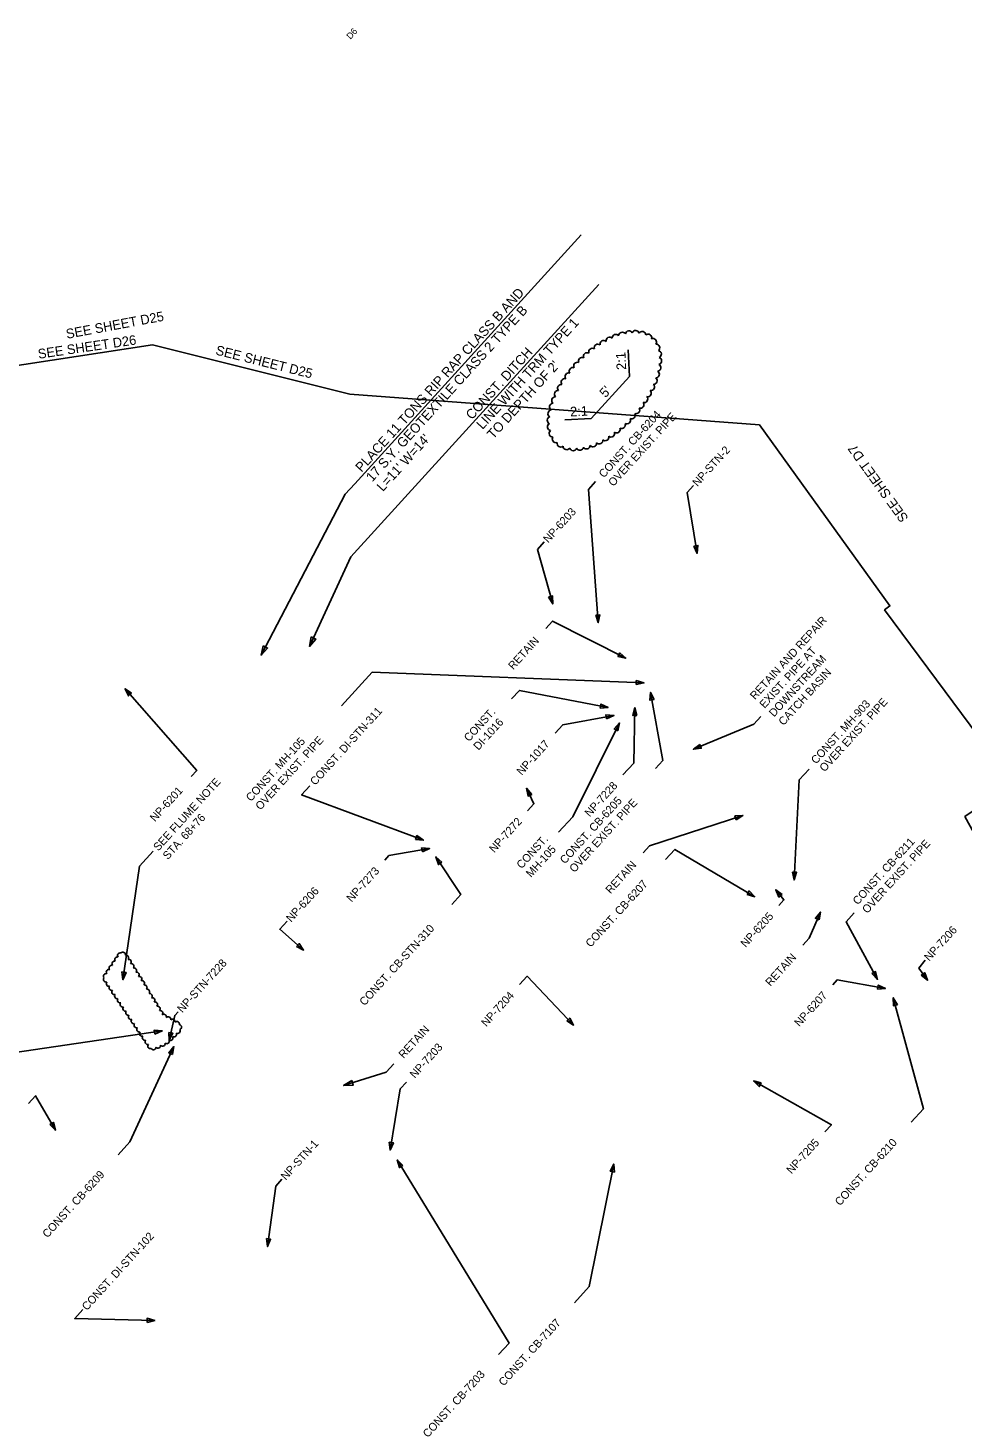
# Model space of a CAD drawing. Extents: x 1608866 to 1610566, y 1091738 to 1093850.
# Drawn here: x 1609658 to 1610242, y 1092975 to 1093850 of the extents above; entities that cross this region are included whole.
import ezdxf

# ---------------------------------------------------------------- set-up
doc = ezdxf.new("R2010")
doc.units = 0
for name, color, linetype in [('Default', 7, 'Continuous'), ('Level 27', 7, 'Continuous'), ('Plan_Clip', 7, 'Continuous'), ('RD_SHT_Bndy', 7, 'Continuous'), ('RD_SHT_MatchLine', 7, 'Continuous'), ('RD_TX_Drainage', 7, 'Continuous')]:
    doc.layers.add(name, color=color, linetype=linetype)

msp = doc.modelspace()

# ---------------------------------------------------------------- linework, layer by layer
at = {"layer": 'Default'}
msp.add_lwpolyline([(1610029.9, 1093383.53), (1610036.58, 1093390.87), (1610037.37, 1093425.47)], dxfattribs=at)
msp.add_lwpolyline([(1610038.55, 1093420.61), (1610037.37, 1093425.47), (1610035.97, 1093420.67)], close=True, dxfattribs=at)
at = {"layer": 'Level 27'}
for p, q in [((1610034.03, 1093632.49), (1610033.24, 1093649.09)), ((1610034.03, 1093632.49), (1610010.12, 1093606.2)), ((1610010.12, 1093606.2), (1609993.52, 1093605.42))]:
    msp.add_line(p, q, dxfattribs=at)
for centre, start, end in [((1610033.61, 1093658.68), 25.47578, 170.47578), ((1610037.8, 1093658.89), 15.48659, 160.48659), ((1610014.21, 1093650.33), 52.27043, 197.27043), ((1610017.81, 1093652.65), 48.45134, 193.45134), ((1610021.55, 1093654.71), 44.14815, 189.14815), ((1610025.44, 1093656.45), 39.14001, 184.14001), ((1610029.47, 1093657.81), 33.09132, 178.09132), ((1610041.89, 1093658.27), 2.08013, 147.08013), ((1610045.61, 1093656.61), 344.80506, 129.80506), ((1610048.59, 1093653.89), 325.62249, 110.62249), ((1610050.6, 1093650.35), 308.34742, 93.34742), ((1610004.35, 1093642.1), 62.15062, 207.15062), ((1610007.48, 1093645.03), 59.02235, 204.02235), ((1610010.77, 1093647.78), 55.75745, 200.75745), ((1610051.61, 1093646.33), 294.94096, 79.94096), ((1610051.79, 1093642.15), 284.95177, 69.95177), ((1609998.58, 1093635.76), 68.27724, 213.27724), ((1610001.38, 1093639.01), 65.21387, 210.21387), ((1610050.35, 1093633.8), 271.28754, 56.28754), ((1610051.32, 1093637.94), 277.33623, 62.33623), ((1609991.32, 1093625.16), 78.15719, 223.15719), ((1609993.53, 1093628.83), 74.6705, 219.6705), ((1609995.96, 1093632.36), 71.40568, 216.40568), ((1610047.29, 1093625.84), 261.97621, 46.97621), ((1610048.98, 1093629.76), 266.27939, 51.27939), ((1609987.65, 1093617.44), 86.27835, 231.27835), ((1609989.35, 1093621.36), 81.97595, 226.97595), ((1610043.1, 1093618.37), 254.6701, 39.6701), ((1610045.31, 1093622.04), 258.15711, 43.15711), ((1609985.31, 1093609.26), 97.33161, 242.33161), ((1609986.28, 1093613.4), 91.28497, 236.28497), ((1610035.25, 1093608.19), 245.21367, 30.21367), ((1610038.06, 1093611.44), 248.27692, 33.27692), ((1610040.68, 1093614.84), 251.4052, 36.4052), ((1609984.85, 1093605.06), 104.94501, 249.94501), ((1609985.02, 1093600.87), 114.93498, 259.93498), ((1610025.86, 1093599.42), 235.75705, 20.75705), ((1610029.15, 1093602.17), 239.02187, 24.02187), ((1610032.28, 1093605.1), 242.15031, 27.15031), ((1609986.03, 1093596.86), 128.3407, 273.3407), ((1609988.04, 1093593.31), 145.61713, 290.61713), ((1609991.03, 1093590.59), 164.81042, 309.81042), ((1610015.08, 1093592.49), 224.14919, 9.14919), ((1610018.83, 1093594.55), 228.4516, 13.4516), ((1610022.42, 1093596.87), 232.27036, 17.27036), ((1609994.75, 1093588.93), 182.08684, 327.08684), ((1609998.84, 1093588.31), 195.49257, 340.49257), ((1610003.02, 1093588.53), 205.48254, 350.48254), ((1610007.16, 1093589.39), 213.09594, 358.09594), ((1610011.19, 1093590.75), 219.14258, 4.14258)]:
    msp.add_arc(centre, 2.27, start, end, dxfattribs=at)
at = {"layer": 'Plan_Clip'}
msp.add_lwpolyline([(1608865.54, 1092773.4), (1609640.55, 1093637.57), (1609735.98, 1093652.25), (1609859.36, 1093621.37), (1610115.12, 1093602.27), (1610196.6, 1093489.1), (1610193.26, 1093486.62), (1610273.82, 1093378.23), (1610243.45, 1093357.42), (1610329.63, 1093200.98), (1610402.66, 1093068.39), (1609510.9, 1092089.32), (1609496.88, 1092101.66), (1609489.45, 1092107.95), (1609480.57, 1092093.35), (1609450.27, 1092115.95), (1609446.7, 1092110.96), (1609379.78, 1092159.35), (1609135.57, 1092347.04), (1609149.57, 1092364.39), (1609089.98, 1092453.43), (1608942.04, 1092657.59), (1608947.36, 1092661.14)], close=True, dxfattribs=at)
msp.add_lwpolyline([(1608865.54, 1092773.4), (1609640.55, 1093637.57), (1609735.98, 1093652.25), (1609859.36, 1093621.37), (1610115.12, 1093602.27), (1610196.6, 1093489.1), (1610193.26, 1093486.62), (1610273.82, 1093378.23), (1610243.45, 1093357.42), (1610329.63, 1093200.98), (1610402.66, 1093068.39), (1609510.9, 1092089.32), (1609496.88, 1092101.66), (1609489.45, 1092107.95), (1609480.57, 1092093.35), (1609450.27, 1092115.95), (1609446.7, 1092110.96), (1609379.78, 1092159.35), (1609135.57, 1092347.04), (1609149.57, 1092364.39), (1609089.98, 1092453.43), (1608942.04, 1092657.59), (1608947.36, 1092661.14)], close=True, dxfattribs=at)
msp.add_lwpolyline([(1608865.54, 1092773.4), (1609640.55, 1093637.57), (1609735.98, 1093652.25), (1609859.36, 1093621.37), (1610115.12, 1093602.27), (1610196.6, 1093489.1), (1610193.26, 1093486.62), (1610273.82, 1093378.23), (1610243.45, 1093357.42), (1610329.63, 1093200.98), (1610402.66, 1093068.39), (1609510.9, 1092089.32), (1609496.88, 1092101.66), (1609489.45, 1092107.95), (1609480.57, 1092093.35), (1609450.27, 1092115.95), (1609446.7, 1092110.96), (1609379.78, 1092159.35), (1609135.57, 1092347.04), (1609149.57, 1092364.39), (1609089.98, 1092453.43), (1608942.04, 1092657.59), (1608947.36, 1092661.14)], close=True, dxfattribs=at)
msp.add_lwpolyline([(1608865.54, 1092773.4), (1609640.55, 1093637.57), (1609735.98, 1093652.25), (1609859.36, 1093621.37), (1610115.12, 1093602.27), (1610196.6, 1093489.1), (1610193.26, 1093486.62), (1610273.82, 1093378.23), (1610243.45, 1093357.42), (1610329.63, 1093200.98), (1610402.66, 1093068.39), (1609510.9, 1092089.32), (1609496.88, 1092101.66), (1609489.45, 1092107.95), (1609480.57, 1092093.35), (1609450.27, 1092115.95), (1609446.7, 1092110.96), (1609379.78, 1092159.35), (1609135.57, 1092347.04), (1609149.57, 1092364.39), (1609089.98, 1092453.43), (1608942.04, 1092657.59), (1608947.36, 1092661.14)], close=True, dxfattribs=at)
msp.add_lwpolyline([(1608865.54, 1092773.4), (1609640.55, 1093637.57), (1609735.98, 1093652.25), (1609859.36, 1093621.37), (1610115.12, 1093602.27), (1610196.6, 1093489.1), (1610193.26, 1093486.62), (1610273.82, 1093378.23), (1610243.45, 1093357.42), (1610329.63, 1093200.98), (1610402.66, 1093068.39), (1609510.9, 1092089.32), (1609496.88, 1092101.66), (1609489.45, 1092107.95), (1609480.57, 1092093.35), (1609450.27, 1092115.95), (1609446.7, 1092110.96), (1609379.78, 1092159.35), (1609135.57, 1092347.04), (1609149.57, 1092364.39), (1609089.98, 1092453.43), (1608942.04, 1092657.59), (1608947.36, 1092661.14)], close=True, dxfattribs=at)
msp.add_lwpolyline([(1608865.54, 1092773.4), (1609640.55, 1093637.57), (1609735.98, 1093652.25), (1609859.36, 1093621.37), (1610115.12, 1093602.27), (1610196.6, 1093489.1), (1610193.26, 1093486.62), (1610273.82, 1093378.23), (1610243.45, 1093357.42), (1610329.63, 1093200.98), (1610402.66, 1093068.39), (1609510.9, 1092089.32), (1609496.88, 1092101.66), (1609489.45, 1092107.95), (1609480.57, 1092093.35), (1609450.27, 1092115.95), (1609446.7, 1092110.96), (1609379.78, 1092159.35), (1609135.57, 1092347.04), (1609149.57, 1092364.39), (1609089.98, 1092453.43), (1608942.04, 1092657.59), (1608947.36, 1092661.14)], close=True, dxfattribs=at)
msp.add_lwpolyline([(1608865.54, 1092773.4), (1609640.55, 1093637.57), (1609735.98, 1093652.25), (1609859.36, 1093621.37), (1610115.12, 1093602.27), (1610196.6, 1093489.1), (1610193.26, 1093486.62), (1610273.82, 1093378.23), (1610243.45, 1093357.42), (1610329.63, 1093200.98), (1610402.66, 1093068.39), (1609510.9, 1092089.32), (1609496.88, 1092101.66), (1609489.45, 1092107.95), (1609480.57, 1092093.35), (1609450.27, 1092115.95), (1609446.7, 1092110.96), (1609379.78, 1092159.35), (1609135.57, 1092347.04), (1609149.57, 1092364.39), (1609089.98, 1092453.43), (1608942.04, 1092657.59), (1608947.36, 1092661.14)], close=True, dxfattribs=at)
msp.add_lwpolyline([(1608865.54, 1092773.4), (1609640.55, 1093637.57), (1609735.98, 1093652.25), (1609859.36, 1093621.37), (1610115.12, 1093602.27), (1610196.6, 1093489.1), (1610193.26, 1093486.62), (1610273.82, 1093378.23), (1610243.45, 1093357.42), (1610329.63, 1093200.98), (1610402.66, 1093068.39), (1609510.9, 1092089.32), (1609496.88, 1092101.66), (1609489.45, 1092107.95), (1609480.57, 1092093.35), (1609450.27, 1092115.95), (1609446.7, 1092110.96), (1609379.78, 1092159.35), (1609135.57, 1092347.04), (1609149.57, 1092364.39), (1609089.98, 1092453.43), (1608942.04, 1092657.59), (1608947.36, 1092661.14)], close=True, dxfattribs=at)
at = {"layer": 'RD_TX_Drainage'}
for p, q in [((1610003.81, 1093720.88), (1609862.33, 1093565.32)), ((1610014.76, 1093689.89), (1609935.98, 1093603.27))]:
    msp.add_line(p, q, dxfattribs=at)
for points in [[(1609935.98, 1093603.27), (1609859.96, 1093519.69), (1609834.12, 1093463.76)], [(1609862.33, 1093565.32), (1609856.42, 1093558.82), (1609803.85, 1093458.34)], [(1610012.74, 1093566.71), (1610008.29, 1093561.81), (1610014.5, 1093478.62)], [(1610073.91, 1093564.26), (1610069.92, 1093559.88), (1610076.19, 1093521.87)], [(1609980.7, 1093529.02), (1609976.45, 1093524.35), (1609986.01, 1093490.29)], [(1609981.71, 1093474.91), (1609985.93, 1093479.56), (1610031.66, 1093456.35)], [(1609854.19, 1093426.57), (1609873.31, 1093447.59), (1610042.94, 1093440.99)], [(1609760.28, 1093382.5), (1609763.64, 1093386.19), (1609718.87, 1093437.35)], [(1609960.34, 1093430.93), (1609965.23, 1093436.31), (1610020.56, 1093425.59)], [(1610050.3, 1093387.54), (1610054.89, 1093392.59), (1610047.15, 1093435.08)], [(1609987.45, 1093409.54), (1609992.28, 1093414.85), (1610024.19, 1093420.71)], [(1610116.07, 1093420.03), (1610111.64, 1093415.15), (1610073.85, 1093399.54)], [(1609989.7, 1093347.67), (1609998.5, 1093357.35), (1610027.72, 1093415.96)], [(1610146.1, 1093387.13), (1610139.95, 1093380.37), (1610136.78, 1093317.92)], [(1609834.28, 1093376.6), (1609829.18, 1093370.98), (1609905.23, 1093342.72)], [(1609970.26, 1093361.13), (1609974.24, 1093365.52), (1609969.69, 1093375.16)], [(1610042.48, 1093334.91), (1610046.4, 1093339.21), (1610104.79, 1093358.16)], [(1609881.19, 1093330.27), (1609883.75, 1093333.08), (1609909.12, 1093337.49)], [(1609736.51, 1093335.8), (1609727.95, 1093326.39), (1609717.56, 1093255.5)], [(1609922.92, 1093302.5), (1609928.57, 1093308.71), (1609913.01, 1093332.25)], [(1610056.56, 1093330.65), (1610062.32, 1093336.98), (1610112.19, 1093307.42)], [(1610127.34, 1093301.96), (1610130.44, 1093305.38), (1610125.3, 1093311.72)], [(1610142.33, 1093277.13), (1610146.25, 1093281.43), (1610153.21, 1093297.83)], [(1610174.28, 1093297.23), (1610169.26, 1093291.72), (1610188.87, 1093255.71)], [(1609820.13, 1093292.08), (1609815.54, 1093287.04), (1609830.46, 1093274.01)], [(1610218.69, 1093267.71), (1610214.69, 1093262.69), (1610220.13, 1093255.23)], [(1609965.29, 1093252.45), (1609970.06, 1093257.7), (1609999.04, 1093227.2)], [(1610160.91, 1093252.43), (1610163.61, 1093255.4), (1610193.82, 1093250.09)], [(1610209.87, 1093166.5), (1610217.52, 1093174.91), (1610198.75, 1093244.25)], [(1609752.08, 1093235.51), (1609749.96, 1093233.19), (1609746.51, 1093217.64)], [(1609644.62, 1093205.17), (1609648.79, 1093209.76), (1609742.13, 1093223.53)], [(1609714.62, 1093146.19), (1609721.98, 1093154.28), (1609749.4, 1093213.76)], [(1609886.71, 1093202.91), (1609882.08, 1093197.82), (1609855.42, 1093189.41)], [(1609894.69, 1093191.57), (1609890.8, 1093187.29), (1609884.44, 1093149.08)], [(1610155.96, 1093160.45), (1610160.07, 1093164.97), (1610111.46, 1093192.29)], [(1609658.61, 1093178.3), (1609662.94, 1093183.07), (1609675.47, 1093161.51)], [(1609952.21, 1093021.36), (1609958.75, 1093028.55), (1609888.87, 1093142.97)], [(1609999.57, 1093053.57), (1610008.85, 1093063.77), (1610024.18, 1093140.34)], [(1609816.83, 1093130.86), (1609813, 1093126.65), (1609807.9, 1093088.82)], [(1609692.58, 1093049.44), (1609687.5, 1093043.86), (1609737.47, 1093042.58)]]:
    msp.add_lwpolyline(points, dxfattribs=at)
for points in [[(1610074.13, 1093526.42), (1610076.19, 1093521.87), (1610076.68, 1093526.85)], [(1609983.46, 1093494.59), (1609986.01, 1093490.29), (1609985.95, 1093495.29)], [(1610012.85, 1093483.34), (1610014.5, 1093478.62), (1610015.43, 1093483.54)], [(1609835.14, 1093469.67), (1609834.12, 1093463.76), (1609837.96, 1093468.37)], [(1609805.16, 1093464.19), (1609803.85, 1093458.34), (1609807.91, 1093462.75)], [(1610026.76, 1093457.39), (1610031.66, 1093456.35), (1610027.94, 1093459.69)], [(1610038.06, 1093439.88), (1610042.94, 1093440.99), (1610038.16, 1093442.47)], [(1609723.02, 1093434.57), (1609718.87, 1093437.35), (1609721.08, 1093432.86)], [(1610049.29, 1093430.56), (1610047.15, 1093435.08), (1610046.75, 1093430.1)], [(1610015.58, 1093425.24), (1610020.56, 1093425.59), (1610016.07, 1093427.78)], [(1610019.68, 1093418.57), (1610024.19, 1093420.71), (1610019.21, 1093421.11)], [(1610026.72, 1093411.06), (1610027.72, 1093415.96), (1610024.41, 1093412.22)], [(1610077.82, 1093402.58), (1610073.85, 1093399.54), (1610078.81, 1093400.19)], [(1609972.92, 1093371.35), (1609969.69, 1093375.16), (1609970.58, 1093370.24)], [(1610100.6, 1093355.43), (1610104.79, 1093358.16), (1610099.8, 1093357.9)], [(1609900.26, 1093343.19), (1609905.23, 1093342.72), (1609901.16, 1093345.61)], [(1609904.58, 1093335.38), (1609909.12, 1093337.49), (1609904.14, 1093337.93)], [(1609916.75, 1093328.94), (1609913.01, 1093332.25), (1609914.59, 1093327.51)], [(1610135.74, 1093322.81), (1610136.78, 1093317.92), (1610138.32, 1093322.68)], [(1610129.35, 1093308.78), (1610125.3, 1093311.72), (1610127.34, 1093307.15)], [(1610107.37, 1093308.77), (1610112.19, 1093307.42), (1610108.69, 1093311)], [(1610152.51, 1093292.88), (1610153.21, 1093297.83), (1610150.13, 1093293.89)], [(1609825.97, 1093276.21), (1609830.46, 1093274.01), (1609827.67, 1093278.16)], [(1609716.98, 1093260.46), (1609717.56, 1093255.5), (1609719.54, 1093260.09)], [(1610185.42, 1093259.33), (1610188.87, 1093255.71), (1610187.7, 1093260.57)], [(1610216.24, 1093258.37), (1610220.13, 1093255.23), (1610218.33, 1093259.9)], [(1610188.84, 1093249.65), (1610193.82, 1093250.09), (1610189.29, 1093252.2)], [(1610201.26, 1093239.93), (1610198.75, 1093244.25), (1610198.77, 1093239.25)], [(1609737.54, 1093221.55), (1609742.13, 1093223.53), (1609737.16, 1093224.11)], [(1609994.77, 1093229.81), (1609999.04, 1093227.2), (1609996.65, 1093231.6)], [(1609746.29, 1093222.64), (1609746.51, 1093217.64), (1609748.82, 1093222.08)], [(1609748.55, 1093208.83), (1609749.4, 1093213.76), (1609746.2, 1093209.92)], [(1609860.48, 1093192.63), (1609855.42, 1093189.41), (1609861.42, 1093189.67)], [(1610116.31, 1093191.05), (1610111.46, 1093192.29), (1610115.04, 1093188.8)], [(1609671.93, 1093165.03), (1609675.47, 1093161.51), (1609674.17, 1093166.33)], [(1609883.96, 1093154.06), (1609884.44, 1093149.08), (1609886.51, 1093153.64)], [(1609892.49, 1093139.52), (1609888.87, 1093142.97), (1609890.28, 1093138.18)], [(1610024.5, 1093135.35), (1610024.18, 1093140.34), (1610021.96, 1093135.85)], [(1609807.26, 1093093.78), (1609807.9, 1093088.82), (1609809.83, 1093093.43)], [(1609732.61, 1093041.41), (1609737.47, 1093042.58), (1609732.67, 1093043.99)]]:
    msp.add_lwpolyline(points, close=True, dxfattribs=at)
for centre, start, end in [((1609714.1, 1093268.09), 73.34641, 218.34641), ((1609715.85, 1093270.67), 73.34641, 218.34641), ((1609717.51, 1093271.11), 351.27368, 136.27368), ((1609719.52, 1093269.27), 319.10662, 104.10662), ((1609721.16, 1093266.61), 319.10662, 104.10662), ((1609707.08, 1093257.74), 73.34641, 218.34641), ((1609708.84, 1093260.33), 73.34641, 218.34641), ((1609710.59, 1093262.91), 73.34641, 218.34641), ((1609712.35, 1093265.5), 73.34641, 218.34641), ((1609722.8, 1093263.95), 319.10662, 104.10662), ((1609724.44, 1093261.29), 319.10662, 104.10662), ((1609726.07, 1093258.63), 319.10662, 104.10662), ((1609707.07, 1093255.7), 141.18178, 286.18178), ((1609708.81, 1093253.1), 141.18178, 286.18178), ((1609710.54, 1093250.5), 141.18178, 286.18178), ((1609727.71, 1093255.97), 319.10662, 104.10662), ((1609729.35, 1093253.31), 319.10662, 104.10662), ((1609730.99, 1093250.64), 319.10662, 104.10662), ((1609712.27, 1093247.9), 141.18178, 286.18178), ((1609714.01, 1093245.3), 141.18178, 286.18178), ((1609715.74, 1093242.7), 141.18178, 286.18178), ((1609717.47, 1093240.1), 141.18178, 286.18178), ((1609732.62, 1093247.98), 319.10662, 104.10662), ((1609734.26, 1093245.32), 319.10662, 104.10662), ((1609735.9, 1093242.66), 319.10662, 104.10662), ((1609737.54, 1093240), 319.10662, 104.10662), ((1609719.2, 1093237.5), 141.18178, 286.18178), ((1609720.94, 1093234.9), 141.18178, 286.18178), ((1609722.67, 1093232.3), 141.18178, 286.18178), ((1609739.17, 1093237.34), 319.10662, 104.10662), ((1609740.81, 1093234.68), 319.10662, 104.10662), ((1609743.08, 1093232.33), 344.09865, 129.09865), ((1609745.8, 1093230.71), 349.24577, 134.24577), ((1609724.4, 1093229.7), 141.18178, 286.18178), ((1609726.14, 1093227.1), 141.18178, 286.18178), ((1609727.87, 1093224.5), 141.18178, 286.18178), ((1609748.55, 1093229.23), 349.24577, 134.24577), ((1609751.31, 1093227.75), 349.24577, 134.24577), ((1609751.67, 1093223.6), 241.68037, 26.68037), ((1609752.54, 1093225.86), 291.60046, 76.60046), ((1609729.6, 1093221.9), 141.18178, 286.18178), ((1609731.33, 1093219.3), 141.18178, 286.18178), ((1609733.07, 1093216.7), 141.18178, 286.18178), ((1609734.8, 1093214.1), 141.18178, 286.18178), ((1609742.39, 1093215.64), 220.59323, 5.59323), ((1609744.9, 1093217.18), 237.32109, 22.32109), ((1609747.19, 1093219.24), 241.68037, 26.68037), ((1609749.43, 1093221.42), 241.68037, 26.68037), ((1609736.63, 1093213.41), 212.74988, 357.74988), ((1609739.51, 1093214.41), 220.59323, 5.59323)]:
    msp.add_arc(centre, 1.64, start, end, dxfattribs=at)

# ---------------------------------------------------------------- texts
at = {"layer": 'Default'}
msp.add_text('NP-7228', height=5, rotation=47.71377, dxfattribs=at).set_placement((1610009.09, 1093356.93))
at = {"layer": 'Level 27'}
for s, rotation, p in [('2:1', 92.71377, (1610031.94, 1093636.67)), ("5'", 47.71377, (1610019.01, 1093618.78)), ('2:1', 2.71377, (1609996.98, 1093607.44))]:
    msp.add_text(s, height=6, rotation=rotation, dxfattribs=at).set_placement(p)
at = {"layer": 'RD_SHT_Bndy'}
msp.add_text('D6', height=4, rotation=47.71377, dxfattribs=at).set_placement((1609859.71, 1093842.76))
at = {"layer": 'RD_SHT_MatchLine'}
for s, rotation, p in [('SEE SHEET D25', 10.54068, (1609682.59, 1093655.94)), ('SEE SHEET D26', 8.35833, (1609664.93, 1093643.45)), ('SEE SHEET D25', 345.93804, (1609775.06, 1093646.19)), ('SEE SHEET D7', 125.75611, (1610208.45, 1093544.02))]:
    msp.add_text(s, height=6, rotation=rotation, dxfattribs=at).set_placement(p)
at = {"layer": 'RD_TX_Drainage'}
for s, height, p in [('PLACE 11 TONS RIP RAP CLASS B AND', 6, (1609866.61, 1093572.25)), ('17 S.Y. GEOTEXTILE CLASS 2 TYPE B', 6, (1609873.26, 1093566.2)), ('LINE WITH TRM TYPE 1', 6, (1609942.2, 1093598.96)), ('CONST. DITCH ', 6, (1609935.54, 1093605.02)), ("TO DEPTH OF 2'", 6, (1609948.86, 1093592.91)), ('CONST. CB-6204', 5, (1610017.96, 1093568.73)), ('OVER EXIST. PIPE', 5, (1610023.88, 1093563.35)), ("L=11' W=14'", 6, (1609879.92, 1093560.14)), ('NP-STN-2', 5, (1610076.43, 1093563.32)), ('NP-6203', 5, (1609983.23, 1093528.08)), ('RETAIN AND REPAIR', 5, (1610112.41, 1093430.12)), ('RETAIN', 5, (1609961.38, 1093448.85)), ('EXIST. PIPE AT ', 5, (1610118.33, 1093424.74)), ('DOWNSTREAM ', 5, (1610124.25, 1093419.36)), ('CATCH BASIN', 5, (1610130.17, 1093413.98)), ('CONST. DI-STN-311', 5, (1609837.65, 1093376.59)), ('CONST. MH-903', 5, (1610150.49, 1093389.89)), ('OVER EXIST. PIPE', 5, (1610155.82, 1093385.04)), ('CONST.', 5, (1609933.72, 1093403.89)), ('DI-1016', 5, (1609939.64, 1093398.51)), ('OVER EXIST. PIPE', 5, (1609803.48, 1093361.15)), ('CONST. MH-105', 5, (1609797.56, 1093366.53)), ('NP-1017', 5, (1609966.64, 1093382.94)), ('SEE FLUME NOTE', 5, (1609739.7, 1093335.6)), ('NP-6201', 5, (1609737.63, 1093353.88)), ('CONST. CB-6205', 5, (1609993.66, 1093327.51)), ('OVER EXIST. PIPE', 5, (1609999.58, 1093322.12)), ('STA. 68+76', 5, (1609745.62, 1093330.21)), ('NP-7272', 5, (1609949.45, 1093334.54)), ('CONST.', 5, (1609966.58, 1093324.48)), ('MH-105', 5, (1609972.49, 1093319.1)), ('CONST. CB-6211', 5, (1610176.54, 1093301.94)), ('OVER EXIST. PIPE', 5, (1610182.46, 1093296.56)), ('RETAIN', 5, (1610022.16, 1093308.85)), ('NP-7273', 5, (1609860.38, 1093303.67)), ('NP-6206', 5, (1609822.66, 1093291.14)), ('CONST. CB-6207', 5, (1610009.69, 1093275.41)), ('NP-6205', 5, (1610106.53, 1093275.37)), ('CONST. CB-STN-310', 5, (1609868.47, 1093238.91)), ('NP-7206', 5, (1610221.21, 1093266.77)), ('NP-STN-7228', 5, (1609754.6, 1093234.57)), ('RETAIN', 5, (1610122.01, 1093251.07)), ('NP-7204', 5, (1609944.48, 1093225.86)), ('NP-6207', 5, (1610140.1, 1093225.83)), ('RETAIN', 5, (1609892.9, 1093206)), ('NP-7203', 5, (1609899.91, 1093193.59)), ('NP-STN-1', 5, (1609819.35, 1093129.92)), ('NP-7205', 5, (1610135.15, 1093133.85)), ('CONST. CB-6210', 5, (1610165.43, 1093113.93)), ('CONST. CB-6209', 5, (1609670.45, 1093093.9)), ('CONST. DI-STN-102', 5, (1609695.1, 1093048.5)), ('CONST. CB-7107', 5, (1609955.4, 1093001.28)), ('CONST. CB-7203', 5, (1609908.04, 1092969.08))]:
    msp.add_text(s, height=height, rotation=47.71377, dxfattribs=at).set_placement(p)

doc.saveas('drawing.dxf')
